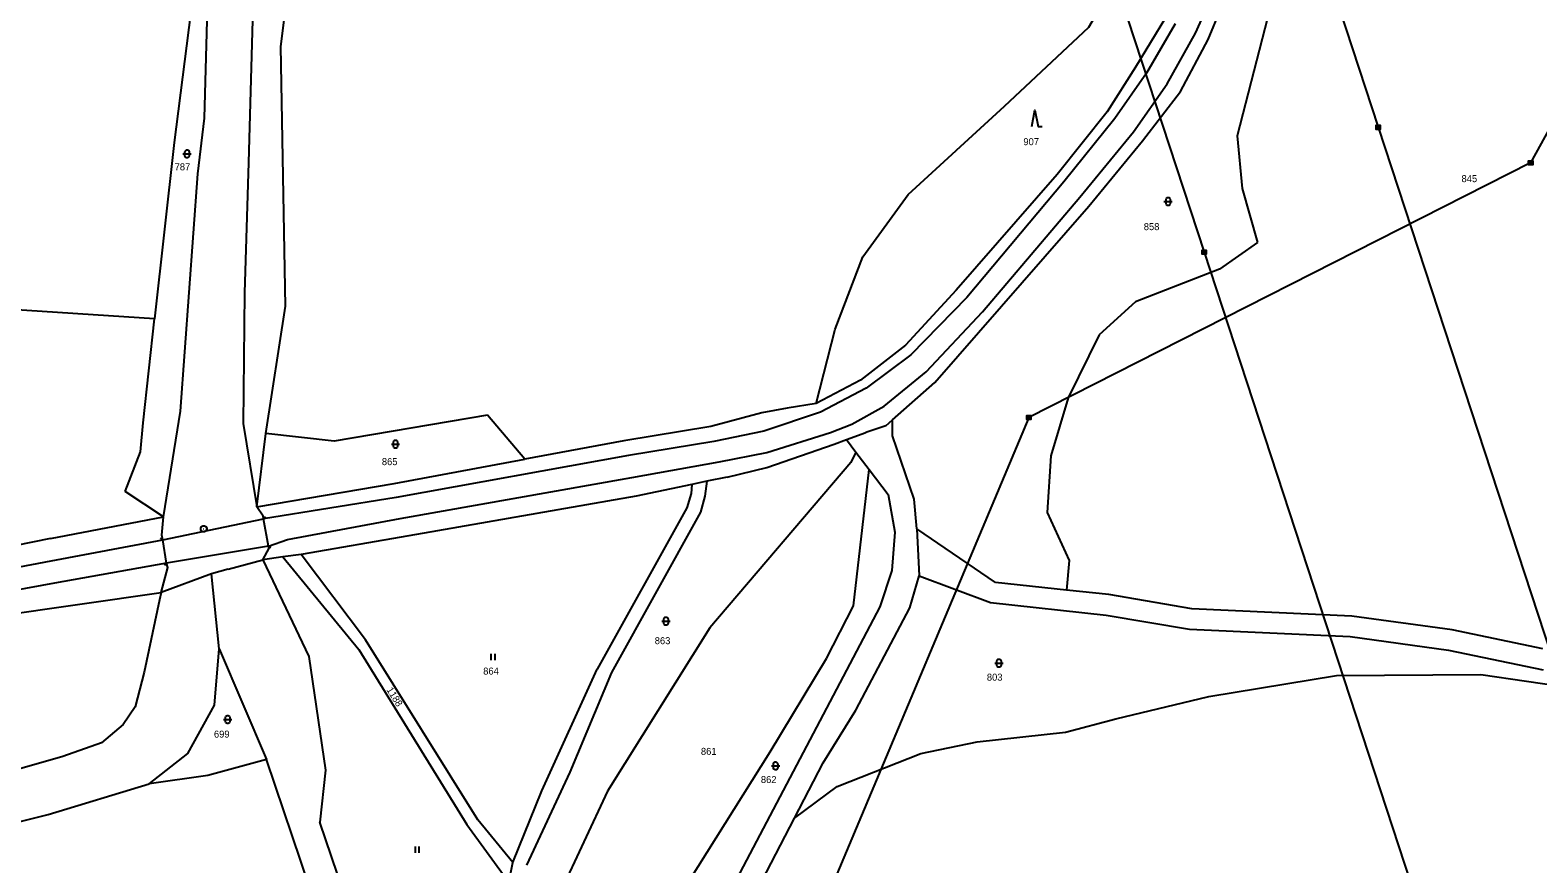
# Model space of a CAD drawing. Extents: x -812394 to -807601, y -1013098 to -1009266.
# Drawn here: x -809418.3 to -809052.3, y -1010781.2 to -1010578.9 of the extents above; entities that cross this region are included whole.
import ezdxf

# ---------------------------------------------------------------- set-up
doc = ezdxf.new("R2010")
doc.units = 0
for name, color, linetype in [('KN_HRANICE', 7, 'Continuous'), ('KN_KULTURY', 7, 'Continuous'), ('KN_MEZNIKY', 7, 'Continuous'), ('KN_PARCELY', 7, 'Continuous'), ('KN_SLUCKY', 7, 'Continuous'), ('KN_VEDENI', 7, 'Continuous')]:
    doc.layers.add(name, color=color, linetype=linetype)

# ---------------------------------------------------------------- blocks, each defined once
blk = doc.blocks.new('101')
blk.add_line((-0.05, 0), (0.05, 0))
blk.add_lwpolyline([(0.19, 0.72), (0.53, 0.53), (0.72, 0.19), (0.72, -0.2), (0.53, -0.54), (0.19, -0.73), (-0.2, -0.73), (-0.54, -0.54), (-0.73, -0.2), (-0.73, 0.19), (-0.54, 0.53), (-0.2, 0.72), (0.19, 0.72)])
blk = doc.blocks.new('306')
for p, q in [((-0.5, 1.5), (-0.5, 0)), ((0.5, 0), (0.5, 1.5))]:
    blk.add_line(p, q)
blk = doc.blocks.new('308')
blk.add_lwpolyline([(-0.75, 0), (0, 4), (0.75, 0), (1.75, 0)])
blk = doc.blocks.new('316')
for points in [[(-1, 1), (0.27, 1), (1, 1)], [(-0.5, 1.5), (-0.4, 1.79), (-0.15, 1.97), (0.16, 1.97), (0.41, 1.79), (0.51, 1.5), (0.51, 0.5), (0.41, 0.21), (0.16, 0.03), (-0.15, 0.03), (-0.4, 0.21), (-0.5, 0.5), (-0.5, 1.5)]]:
    blk.add_lwpolyline(points)
blk = doc.blocks.new('4201')
blk.add_line((0, 0), (-0.5, -0.5))
blk = doc.blocks.new('602')
blk.add_lwpolyline([(-0.5, 0.5), (0.5, 0.5), (0.5, -0.5), (-0.5, -0.5), (-0.5, 0.5), (-0.44, 0.44), (0.44, 0.44), (0.44, 0.36), (-0.44, 0.36), (-0.44, 0.28), (0.44, 0.28), (0.44, 0.2), (-0.44, 0.2), (-0.44, 0.12), (0.44, 0.12), (0.44, 0.04), (-0.44, 0.04), (-0.44, -0.04), (0.44, -0.04), (0.44, -0.12), (-0.44, -0.12), (-0.44, -0.2), (0.44, -0.2), (0.44, -0.28), (-0.44, -0.28), (-0.44, -0.36), (0.44, -0.36), (0.44, -0.44), (-0.44, -0.44)])

msp = doc.modelspace()

# ---------------------------------------------------------------- linework, layer by layer
at = {"layer": 'KN_HRANICE'}
for p, q in [((-809111.83, -1010552.24), (-809125.24, -1010604.55)), ((-809377.13, -1010557.12), (-809383.35, -1010606.11)), ((-809363.71, -1010556.15), (-809365.25, -1010611.02)), ((-809357.41, -1010582.83), (-809354.36, -1010558.01)), ((-809375.97, -1010600.22), (-809375.07, -1010568.14)), ((-809132.35, -1010581.13), (-809129.18, -1010573.51)), ((-809142.65, -1010575.85), (-809149.94, -1010587.88)), ((-809139.03, -1010593.73), (-809132.35, -1010581.13)), ((-809356.31, -1010645.84), (-809357.41, -1010582.83)), ((-809149.94, -1010587.88), (-809156.85, -1010598.68)), ((-809148.29, -1010605.74), (-809139.03, -1010593.73)), ((-809156.85, -1010598.68), (-809169, -1010613.92)), ((-809377.56, -1010613.76), (-809375.97, -1010600.22)), ((-809383.35, -1010606.11), (-809388.09, -1010648.93)), ((-809161.26, -1010621.62), (-809148.29, -1010605.74)), ((-809125.24, -1010604.55), (-809124.05, -1010617.34)), ((-809381.8, -1010671.36), (-809377.56, -1010613.76)), ((-809365.25, -1010611.02), (-809366.29, -1010642.62)), ((-809169, -1010613.92), (-809193.46, -1010642)), ((-809124.05, -1010617.34), (-809120.37, -1010630.38)), ((-809198.7, -1010664.41), (-809161.26, -1010621.62)), ((-809120.37, -1010630.38), (-809129.56, -1010636.86)), ((-809129.56, -1010636.86), (-809149.97, -1010644.82)), ((-809366.29, -1010642.62), (-809366.56, -1010674.35)), ((-809193.46, -1010642), (-809205.76, -1010655.37)), ((-809388.09, -1010648.93), (-809445.19, -1010645.2)), ((-809361.06, -1010676.78), (-809356.31, -1010645.84)), ((-809149.97, -1010644.82), (-809158.75, -1010652.82)), ((-809390.89, -1010674.22), (-809388.09, -1010648.93)), ((-809158.75, -1010652.82), (-809166.27, -1010668.11)), ((-809205.76, -1010655.37), (-809216.72, -1010663.86)), ((-809216.72, -1010663.86), (-809227.49, -1010669.52)), ((-809208.98, -1010673.47), (-809198.7, -1010664.41)), ((-809227.49, -1010669.52), (-809234.5, -1010670.64)), ((-809166.27, -1010668.11), (-809170.54, -1010682.2)), ((-809385.89, -1010696.99), (-809381.8, -1010671.36)), ((-809307.29, -1010672.33), (-809344.46, -1010678.63)), ((-809298.22, -1010683.04), (-809307.29, -1010672.33)), ((-809240.7, -1010671.73), (-809253.03, -1010675.1)), ((-809234.5, -1010670.64), (-809240.7, -1010671.73)), ((-809391.53, -1010681.27), (-809390.89, -1010674.22)), ((-809366.56, -1010674.35), (-809363.24, -1010694.6)), ((-809363.24, -1010694.6), (-809361.06, -1010676.78)), ((-809344.46, -1010678.63), (-809361.06, -1010676.78)), ((-809253.03, -1010675.1), (-809274.21, -1010678.59)), ((-809220.13, -1010678.26), (-809215.44, -1010676.51)), ((-809210.6, -1010674.9), (-809215.44, -1010676.51)), ((-809210.6, -1010674.9), (-809208.98, -1010673.47)), ((-809208.98, -1010677.34), (-809208.98, -1010673.47)), ((-809274.21, -1010678.59), (-809298.22, -1010683.04)), ((-809239.47, -1010685.01), (-809223.12, -1010679.37)), ((-809223.12, -1010679.37), (-809220.13, -1010678.26)), ((-809220.13, -1010678.26), (-809217.82, -1010681.31)), ((-809203.72, -1010692.71), (-809208.98, -1010677.34)), ((-809395.22, -1010690.85), (-809391.53, -1010681.27)), ((-809219.05, -1010683.79), (-809253.31, -1010723.95)), ((-809217.82, -1010681.31), (-809219.05, -1010683.79)), ((-809217.82, -1010681.31), (-809214.65, -1010685.5)), ((-809170.54, -1010682.2), (-809171.37, -1010695.98)), ((-809249.11, -1010687.36), (-809254.05, -1010688.39)), ((-809249.11, -1010687.36), (-809239.47, -1010685.01)), ((-809218.43, -1010718.59), (-809214.65, -1010685.5)), ((-809214.65, -1010685.5), (-809210.02, -1010691.61)), ((-809385.89, -1010696.99), (-809395.22, -1010690.85)), ((-809254.05, -1010688.39), (-809257.64, -1010689.14)), ((-809254.05, -1010688.39), (-809254.52, -1010692.03)), ((-809254.52, -1010692.03), (-809255.59, -1010695.88)), ((-809210.02, -1010691.61), (-809208.36, -1010700.77)), ((-809203.06, -1010699.92), (-809203.72, -1010692.71)), ((-809413.39, -1010702.26), (-809385.89, -1010696.99)), ((-809360.44, -1010704.12), (-809361.63, -1010697.51)), ((-809255.59, -1010695.88), (-809277.13, -1010734.81)), ((-809171.37, -1010695.98), (-809166.1, -1010707.64)), ((-809413.39, -1010702.26), (-809437.86, -1010707.26)), ((-809208.36, -1010700.77), (-809209.11, -1010710.03)), ((-809183.97, -1010712.92), (-809203.06, -1010699.92)), ((-809203.06, -1010699.92), (-809202.45, -1010711.33)), ((-809385.19, -1010708.29), (-809386.06, -1010702.58)), ((-809370.19, -1010709.75), (-809374.26, -1010710.88)), ((-809370.19, -1010709.75), (-809361.8, -1010707.43)), ((-809356.99, -1010706.69), (-809361.8, -1010707.43)), ((-809361.8, -1010707.43), (-809350.65, -1010730.95)), ((-809352.49, -1010706.15), (-809356.99, -1010706.69)), ((-809356.99, -1010706.69), (-809338.51, -1010729.21)), ((-809336.86, -1010726.87), (-809352.49, -1010706.15)), ((-809166.1, -1010707.64), (-809166.67, -1010714.78)), ((-809374.26, -1010710.88), (-809386.46, -1010715.35)), ((-809372.39, -1010729.01), (-809374.26, -1010710.88)), ((-809209.11, -1010710.03), (-809212.01, -1010718.89)), ((-809204.77, -1010719.08), (-809202.45, -1010711.33)), ((-809202.45, -1010711.33), (-809185.19, -1010717.8)), ((-809166.67, -1010714.78), (-809183.97, -1010712.92)), ((-809434.83, -1010722.26), (-809386.46, -1010715.35)), ((-809386.46, -1010715.35), (-809386.86, -1010717.18)), ((-809156.41, -1010715.89), (-809166.67, -1010714.78)), ((-809136.31, -1010719.31), (-809156.41, -1010715.89)), ((-809212.01, -1010718.89), (-809262.62, -1010814.93)), ((-809225, -1010731.39), (-809218.43, -1010718.59)), ((-809217.89, -1010743.91), (-809204.77, -1010719.08)), ((-809185.19, -1010717.8), (-809157.07, -1010720.85)), ((-809097.41, -1010721.08), (-809136.31, -1010719.31)), ((-809253.31, -1010723.95), (-809278.14, -1010763.62)), ((-809157.07, -1010720.85), (-809136.87, -1010724.29)), ((-809136.87, -1010724.29), (-809097.85, -1010726.06)), ((-809073.09, -1010724.43), (-809097.41, -1010721.08)), ((-809051.04, -1010729.02), (-809073.09, -1010724.43)), ((-809309.65, -1010770.56), (-809336.86, -1010726.87)), ((-809097.85, -1010726.06), (-809073.97, -1010729.35)), ((-809372.39, -1010729.01), (-809360.9, -1010755.91)), ((-809350.65, -1010730.95), (-809346.62, -1010758.53)), ((-809338.51, -1010729.21), (-809312.31, -1010771.66)), ((-809238.67, -1010754.07), (-809225, -1010731.39)), ((-809073.97, -1010729.35), (-809051.02, -1010734.13)), ((-809294.04, -1010763.48), (-809280.64, -1010734.02)), ((-809277.13, -1010734.81), (-809287.3, -1010759.01)), ((-809101.15, -1010735.55), (-809066.09, -1010735.31)), ((-809066.09, -1010735.31), (-809035.42, -1010739.75)), ((-809132.16, -1010740.65), (-809101.15, -1010735.55)), ((-809154.74, -1010746.08), (-809132.16, -1010740.65)), ((-809225.81, -1010756.71), (-809217.89, -1010743.91)), ((-809166.94, -1010749.26), (-809154.74, -1010746.08)), ((-809188.43, -1010751.6), (-809166.94, -1010749.26)), ((-809202.08, -1010754.49), (-809188.43, -1010751.6)), ((-809350.5, -1010786.79), (-809360.9, -1010755.91)), ((-809260.51, -1010788.84), (-809238.67, -1010754.07)), ((-809232.78, -1010770.16), (-809225.81, -1010756.71)), ((-809222.4, -1010762.48), (-809202.08, -1010754.49)), ((-809346.62, -1010758.53), (-809348.01, -1010771.1)), ((-809287.3, -1010759.01), (-809297.76, -1010781.54)), ((-809301.09, -1010780.94), (-809294.04, -1010763.48)), ((-809278.14, -1010763.62), (-809289.64, -1010788.2)), ((-809232.78, -1010770.16), (-809222.4, -1010762.48)), ((-809312.31, -1010771.66), (-809302.07, -1010785.66)), ((-809301.09, -1010780.94), (-809309.65, -1010770.56)), ((-809240.68, -1010785.42), (-809232.78, -1010770.16)), ((-809302.07, -1010785.66), (-809301.09, -1010780.94))]:
    msp.add_line(p, q, dxfattribs=at)
for points in [[(-809227.49, -1010669.52), (-809222.89, -1010651.43), (-809216.16, -1010633.87), (-809205.12, -1010618.75), (-809181.78, -1010597.36), (-809161.27, -1010578.12), (-809154.48, -1010566.46), (-809151.95, -1010550.2), (-809148.31, -1010534.06), (-809144.6, -1010520.48), (-809143.21, -1010500.19), (-809145.36, -1010479.96)], [(-809363.24, -1010694.6), (-809329.9, -1010688.92), (-809298.22, -1010683.04)], [(-809257.64, -1010689.14), (-809271.18, -1010691.97), (-809326.4, -1010701.59), (-809352.49, -1010706.15)], [(-809257.64, -1010689.14), (-809257.8, -1010691.32), (-809258.9, -1010694.81), (-809280.64, -1010734.02)], [(-809361.63, -1010697.51), (-809361.69, -1010696.82), (-809363.24, -1010694.6)], [(-809386.06, -1010702.58), (-809386.34, -1010701.43), (-809385.89, -1010696.99)], [(-809361.8, -1010707.43), (-809360.26, -1010704.65), (-809360.44, -1010704.12)], [(-809386.46, -1010715.35), (-809384.87, -1010709.29), (-809385.19, -1010708.29)], [(-809386.86, -1010717.18), (-809390.64, -1010734.74), (-809392.82, -1010743.13), (-809395.75, -1010747.43), (-809400.98, -1010751.89), (-809410.38, -1010755.21), (-809425.36, -1010759.45), (-809455.87, -1010766.45), (-809482.83, -1010772.6), (-809507.48, -1010779.27)], [(-809389.38, -1010761.78), (-809380.01, -1010754.48), (-809373.51, -1010742.73), (-809372.39, -1010729.01)], [(-809360.9, -1010755.91), (-809375.18, -1010759.76), (-809389.38, -1010761.78)], [(-809429.53, -1010773.18), (-809413.92, -1010769.26), (-809389.38, -1010761.78)], [(-809334.49, -1010811.54), (-809335.27, -1010808.48), (-809348.01, -1010771.1)]]:
    msp.add_lwpolyline(points, dxfattribs=at)
at = {"layer": 'KN_SLUCKY'}
for p, q in [((-809386.06, -1010702.58), (-809361.63, -1010697.51)), ((-809360.44, -1010704.12), (-809385.19, -1010708.29))]:
    msp.add_line(p, q, dxfattribs=at)
for points in [[(-809360.44, -1010704.12), (-809355.84, -1010702.51), (-809328.45, -1010697.39), (-809272.21, -1010687.44), (-809251.05, -1010683.67), (-809239.49, -1010681.41), (-809224.04, -1010676.54), (-809218.8, -1010674.51), (-809210.97, -1010670.13), (-809200.79, -1010661.8), (-809187.11, -1010647.21), (-809163.44, -1010619.45), (-809150.48, -1010603.59), (-809142.31, -1010591.91), (-809135.38, -1010579.58), (-809131.33, -1010570.55)], [(-809140.31, -1010577.36), (-809147.31, -1010589.34), (-809154.97, -1010600.3), (-809167.32, -1010615.7), (-809190.91, -1010643.78), (-809204.52, -1010657.67), (-809215.35, -1010665.74), (-809226.43, -1010671.57), (-809240.16, -1010676.22), (-809252.29, -1010678.72), (-809273.06, -1010682.12), (-809329.44, -1010692.29), (-809361.63, -1010697.51)], [(-809462.54, -1010716.59), (-809456.78, -1010715.47), (-809450.24, -1010714.77), (-809436.78, -1010712.1), (-809413.21, -1010707.7), (-809386.06, -1010702.58)], [(-809385.19, -1010708.29), (-809412.36, -1010713.13), (-809435.74, -1010717.37), (-809462.86, -1010722.22)]]:
    msp.add_lwpolyline(points, dxfattribs=at)
at = {"layer": 'KN_VEDENI'}
for points in [[(-809513.17, -1009474.26), (-809487.03, -1009553.9), (-809382.67, -1009871.8), (-809271.71, -1010210.69), (-809133.29, -1010632.77), (-809030.14, -1010947.95), (-808933.39, -1011241.46), (-808834.45, -1011543.27), (-808752.75, -1011794.76), (-808648.03, -1012113.89), (-808628.65, -1012173.95)], [(-809459.32, -1009478.9), (-809443.45, -1009527.33), (-809325.11, -1009888.46), (-809206.96, -1010248.74), (-809091.05, -1010602.46), (-808974.84, -1010956.85), (-808878.7, -1011250.45), (-808788.3, -1011526.17), (-808705.43, -1011779.25), (-808595.97, -1012112.76), (-808574.72, -1012181.51)], [(-808436.07, -1010405.5), (-808486.59, -1010412.34), (-808533.36, -1010418.3), (-808675.88, -1010426.28), (-808821.29, -1010438.46), (-808966.01, -1010451.39), (-809054.03, -1010611.07), (-809175.87, -1010672.9), (-809225.49, -1010790.89), (-809273.78, -1010909.78), (-809328.04, -1011039.73), (-809401.1, -1011213.98), (-809452.49, -1011335.08), (-809491.27, -1011432.33), (-809530.59, -1011529.94)]]:
    msp.add_lwpolyline(points, dxfattribs=at)

# ---------------------------------------------------------------- block references
at = {"layer": 'KN_KULTURY'}
for name, p in [('308', (-809174.37, -1010602.27)), ('316', (-809380.22, -1010609.92)), ('316', (-809142.05, -1010621.48)), ('316', (-809329.6, -1010680.36)), ('316', (-809263.95, -1010723.33)), ('306', (-809305.94, -1010731.8)), ('316', (-809183.11, -1010733.51)), ('316', (-809370.35, -1010747.22)), ('316', (-809237.32, -1010758.48)), ('306', (-809324.32, -1010778.54))]:
    msp.add_blockref(name, p, dxfattribs=at)
at = {"layer": 'KN_MEZNIKY'}
msp.add_blockref('101', (-809376.15, -1010699.92), dxfattribs=at)
at = {"layer": 'KN_SLUCKY'}
for p, rotation in [((-809361.63, -1010697.51), -174.70544900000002), ((-809386.06, -1010702.58), -76.90155299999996), ((-809360.44, -1010704.12), 104.507502)]:
    msp.add_blockref('4201', p, dxfattribs=dict(at, rotation=rotation))
msp.add_blockref('4201', (-809385.19, -1010708.29), dxfattribs=at)
at = {"layer": 'KN_VEDENI'}
for p in [(-809091.05, -1010602.46), (-809054.03, -1010611.07), (-809133.29, -1010632.77), (-809175.87, -1010672.9)]:
    msp.add_blockref('602', p, dxfattribs=at)

# ---------------------------------------------------------------- texts
at = {"layer": 'KN_PARCELY'}
for s, p in [('907', (-809177.18, -1010606.79)), ('787', (-809383.22, -1010612.9)), ('845', (-809070.81, -1010615.77)), ('858', (-809147.95, -1010627.42)), ('865', (-809332.91, -1010684.46)), ('863', (-809266.67, -1010727.92)), ('864', (-809308.31, -1010735.3)), ('803', (-809186.04, -1010736.78)), ('699', (-809373.68, -1010750.6)), ('861', (-809255.46, -1010754.79)), ('862', (-809240.9, -1010761.63))]:
    msp.add_text(s, height=1.7, dxfattribs=at).set_placement(p)
msp.add_text('1188', height=1.7, rotation=302.006, dxfattribs=at).set_placement((-809331.87, -1010738.99))

doc.saveas('drawing.dxf')
